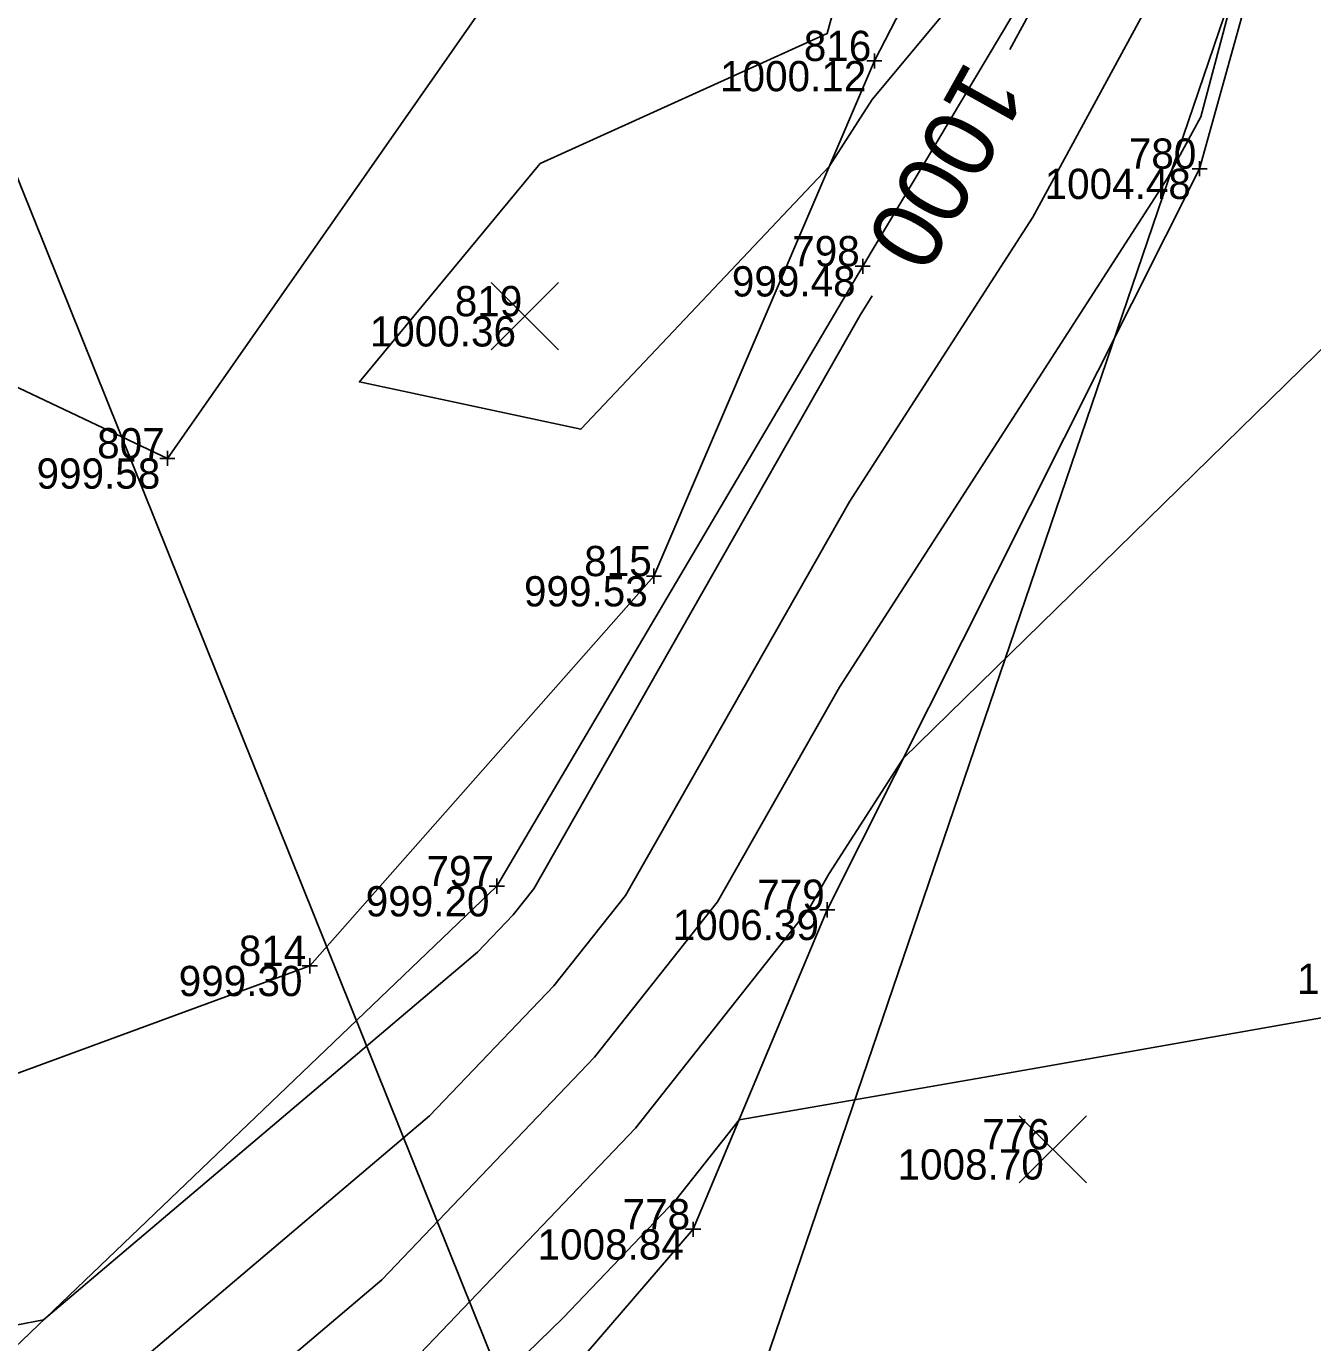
# Model space of a CAD drawing. Extents: x 2354693 to 2355622, y 637071 to 710080.
# Drawn here: x 2355379.4 to 2355430.4, y 709282.3 to 709334.6 of the extents above; entities that cross this region are included whole.
import ezdxf

# ---------------------------------------------------------------- set-up
doc = ezdxf.new("R2010")
doc.units = 0
for name, color, linetype in [('BR_P_Sub_Hidden', 7, 'Continuous'), ('DT_X_Contour_Major', 7, 'Continuous'), ('DT_X_Contour_Minor', 7, 'Continuous'), ('HY_X_Water_Edge', 7, 'Continuous'), ('SV_X_Random_Point', 7, 'Continuous'), ('SV_X_Shot_Marker', 7, 'Continuous'), ('SV_X_Text_Elevation', 7, 'Continuous'), ('SV_X_Text_Name', 7, 'Continuous'), ('SV_X_Toe_of_Slope', 7, 'Continuous'), ('SV_X_Top_of_Bank', 7, 'Continuous'), ('UT_X_Telecom', 7, 'Continuous'), ('VG_X_Tree_Line_Rt', 7, 'Continuous')]:
    doc.layers.add(name, color=color, linetype=linetype)

msp = doc.modelspace()

# ---------------------------------------------------------------- linework, layer by layer
at = {"layer": 'BR_P_Sub_Hidden'}
msp.add_lwpolyline([(2355413.301, 709349.084), (2355412.892, 709348.614), (2355412.203, 709338.148), (2355411.142, 709334.262), (2355399.767, 709329.11), (2355392.596, 709320.444), (2355401.379, 709318.57), (2355411.228, 709328.996), (2355412.93, 709331.646), (2355425.527, 709346.782), (2355418.396, 709333.631)], dxfattribs=at)
at = {"layer": 'DT_X_Contour_Major'}
for points in [[(2355413.301, 709349.084), (2355412.892, 709348.614), (2355412.203, 709338.148), (2355411.142, 709334.262), (2355399.767, 709329.11), (2355392.596, 709320.444), (2355401.379, 709318.57), (2355411.228, 709328.996), (2355412.93, 709331.646), (2355425.527, 709346.782), (2355418.396, 709333.631)], [(2355412.935, 709323.858), (2355412.448, 709323.101), (2355399.508, 709300.34), (2355398.693, 709299.31), (2355397.28, 709297.832), (2355380.065, 709283.245), (2355378.962, 709283.026), (2355376.473, 709281.93), (2355375.148, 709281.346), (2355373.286, 709281.525), (2355372.881, 709278.048), (2355363.645, 709274.356), (2355363.341, 709274.189), (2355362.774, 709274.062), (2355345.265, 709268.035), (2355344.363, 709267.712), (2355344.138, 709267.795), (2355344.093, 709267.669), (2355343.399, 709266.464), (2355342.314, 709266.059), (2355339.268, 709265.779)], [(2355412.935, 709323.858), (2355412.448, 709323.101), (2355399.508, 709300.34), (2355398.693, 709299.31), (2355397.28, 709297.832), (2355380.065, 709283.245), (2355378.962, 709283.026), (2355376.473, 709281.93), (2355375.148, 709281.346), (2355373.286, 709281.525), (2355372.881, 709278.048), (2355363.645, 709274.356), (2355363.341, 709274.189), (2355362.774, 709274.062), (2355345.265, 709268.035), (2355344.363, 709267.712), (2355344.138, 709267.795), (2355344.093, 709267.669), (2355343.399, 709266.464), (2355342.314, 709266.059), (2355339.268, 709265.779)]]:
    msp.add_lwpolyline(points, dxfattribs=at)
at = {"layer": 'DT_X_Contour_Minor'}
for points in [[(2355429.592, 709344.607), (2355425.965, 709330.968), (2355424.646, 709328.535), (2355411.635, 709308.333), (2355406.794, 709299.818), (2355401.922, 709293.664), (2355393.477, 709284.825), (2355385.14, 709277.761)], [(2355429.592, 709344.607), (2355425.965, 709330.968), (2355424.646, 709328.535), (2355411.635, 709308.333), (2355406.794, 709299.818), (2355401.922, 709293.664), (2355393.477, 709284.825), (2355385.14, 709277.761)], [(2355426.171, 709339.659), (2355419.3, 709326.988), (2355412.041, 709315.717), (2355403.151, 709300.079), (2355400.308, 709296.487), (2355395.378, 709291.328), (2355380.244, 709278.504)], [(2355426.171, 709339.659), (2355419.3, 709326.988), (2355412.041, 709315.717), (2355403.151, 709300.079), (2355400.308, 709296.487), (2355395.378, 709291.328), (2355380.244, 709278.504)], [(2355432.983, 709323.929), (2355414.162, 709305.504), (2355411.228, 709300.949), (2355410.437, 709299.557), (2355403.537, 709290.84), (2355391.576, 709278.322)], [(2355432.983, 709323.929), (2355414.162, 709305.504), (2355411.228, 709300.949), (2355410.437, 709299.557), (2355403.537, 709290.84), (2355391.576, 709278.322)], [(2355431.649, 709295.374), (2355417.396, 709292.872), (2355407.651, 709291.174), (2355405.152, 709288.017), (2355400.669, 709283.325), (2355393.85, 709276.684)], [(2355431.649, 709295.374), (2355417.396, 709292.872), (2355407.651, 709291.174), (2355405.152, 709288.017), (2355400.669, 709283.325), (2355393.85, 709276.684)]]:
    msp.add_lwpolyline(points, dxfattribs=at)
at = {"layer": 'HY_X_Water_Edge'}
for points in [[(2355375.813, 709279.177), (2355398.044, 709300.445), (2355412.554, 709325.036), (2355426.374, 709348.201), (2355435.337, 709371.973), (2355446.496, 709387.253), (2355453.681, 709395.052)], [(2355420.269, 709346.848), (2355419.378, 709352.697), (2355410.324, 709349.627), (2355400.891, 709340.195), (2355384.976, 709317.413), (2355376.519, 709321.411), (2355365.865, 709313.284), (2355368.531, 709308.159), (2355374.864, 709304.98), (2355371.771, 709294.557), (2355372.28, 709290.537), (2355390.627, 709297.284), (2355404.273, 709312.742), (2355413.017, 709333.177), (2355419.813, 709346.361)]]:
    msp.add_lwpolyline(points, dxfattribs=at)
at = {"layer": 'SV_X_Random_Point'}
for p, q in [((2355397.82, 709321.717), (2355400.486, 709324.387)), ((2355397.82, 709324.387), (2355400.486, 709321.717)), ((2355418.763, 709288.671), (2355421.429, 709291.341)), ((2355418.763, 709291.341), (2355421.429, 709288.671))]:
    msp.add_line(p, q, dxfattribs=at)
at = {"layer": 'SV_X_Shot_Marker'}
for p, q in [((2355413.317, 709333.177), (2355412.717, 709333.177)), ((2355413.017, 709333.477), (2355413.017, 709332.877)), ((2355425.916, 709329.203), (2355425.916, 709328.603)), ((2355426.216, 709328.903), (2355425.617, 709328.903)), ((2355412.554, 709325.336), (2355412.554, 709324.736)), ((2355412.854, 709325.036), (2355412.254, 709325.036)), ((2355384.976, 709317.713), (2355384.976, 709317.113)), ((2355385.276, 709317.413), (2355384.676, 709317.413)), ((2355404.273, 709313.042), (2355404.273, 709312.442)), ((2355404.573, 709312.742), (2355403.973, 709312.742)), ((2355398.044, 709300.745), (2355398.044, 709300.145)), ((2355398.344, 709300.445), (2355397.744, 709300.445)), ((2355411.149, 709299.806), (2355411.149, 709299.206)), ((2355411.449, 709299.506), (2355410.849, 709299.506)), ((2355390.927, 709297.284), (2355390.327, 709297.284)), ((2355390.627, 709297.584), (2355390.627, 709296.984)), ((2355406.129, 709286.833), (2355405.529, 709286.833)), ((2355405.829, 709287.133), (2355405.829, 709286.533))]:
    msp.add_line(p, q, dxfattribs=at)
at = {"layer": 'SV_X_Toe_of_Slope'}
for points in [[(2355375.813, 709279.177), (2355398.044, 709300.445), (2355412.554, 709325.036), (2355426.374, 709348.201), (2355435.337, 709371.973), (2355446.496, 709387.253), (2355453.681, 709395.052)], [(2355420.269, 709346.848), (2355419.378, 709352.697), (2355410.324, 709349.627), (2355400.891, 709340.195), (2355384.976, 709317.413), (2355376.519, 709321.411), (2355365.865, 709313.284), (2355368.531, 709308.159), (2355374.864, 709304.98), (2355371.771, 709294.557), (2355372.28, 709290.537), (2355390.627, 709297.284), (2355404.273, 709312.742), (2355413.017, 709333.177), (2355419.813, 709346.361)]]:
    msp.add_lwpolyline(points, dxfattribs=at)
at = {"layer": 'SV_X_Top_of_Bank'}
msp.add_lwpolyline([(2355402.872, 709193.943), (2355398.038, 709239.151), (2355396.018, 709270.946), (2355396.928, 709276.495), (2355405.829, 709286.833), (2355411.149, 709299.506), (2355425.916, 709328.903), (2355430.112, 709344.026), (2355451.484, 709369.85), (2355463.891, 709385.714)], dxfattribs=at)
at = {"layer": 'UT_X_Telecom'}
msp.add_line((2355345.904, 709410.895), (2355420.443, 709225.551), dxfattribs=at)
at = {"layer": 'VG_X_Tree_Line_Rt'}
msp.add_lwpolyline([(2355430.113, 709344.442), (2355398.4, 709251.33), (2355397.952, 709252.375), (2355395.764, 709165.299), (2355393.835, 709147.98), (2355384.969, 709102.057), (2355364.4, 709052.049), (2355337.299, 709001.304)], dxfattribs=at)

# ---------------------------------------------------------------- texts
at = {"layer": 'DT_X_Contour_Major'}
msp.add_text('1000', height=2.8, rotation=240.8058, dxfattribs=at).set_placement((2355416.681, 709333.288))
msp.add_text('1000', height=2.8, rotation=240.8058, dxfattribs=at).set_placement((2355416.681, 709333.288))
at = {"layer": 'SV_X_Text_Elevation'}
for s, p in [('1000.12', (2355406.897, 709331.977)), ('1004.48', (2355419.77, 709327.703)), ('999.48', (2355407.365, 709323.836)), ('1000.36', (2355393.003, 709321.852)), ('999.58', (2355379.787, 709316.213)), ('999.53', (2355399.121, 709311.542)), ('999.20', (2355392.843, 709299.245)), ('1006.39', (2355405.02, 709298.306)), ('999.30', (2355385.426, 709296.084)), ('1007.74', (2355429.782, 709296.173)), ('1008.70', (2355413.937, 709288.806)), ('1008.84', (2355399.659, 709285.633))]:
    msp.add_text(s, height=1.2, dxfattribs=at).set_placement(p)
at = {"layer": 'SV_X_Text_Name'}
for s, p in [('816', (2355410.218, 709333.177)), ('780', (2355423.109, 709328.903)), ('798', (2355409.759, 709325.036)), ('819', (2355396.375, 709323.052)), ('807', (2355382.19, 709317.413)), ('815', (2355401.51, 709312.742)), ('797', (2355395.257, 709300.445)), ('779', (2355408.371, 709299.506)), ('814', (2355387.808, 709297.284)), ('776', (2355417.297, 709290.006)), ('778', (2355403.033, 709286.833))]:
    msp.add_text(s, height=1.2, dxfattribs=at).set_placement(p)

doc.saveas('drawing.dxf')
